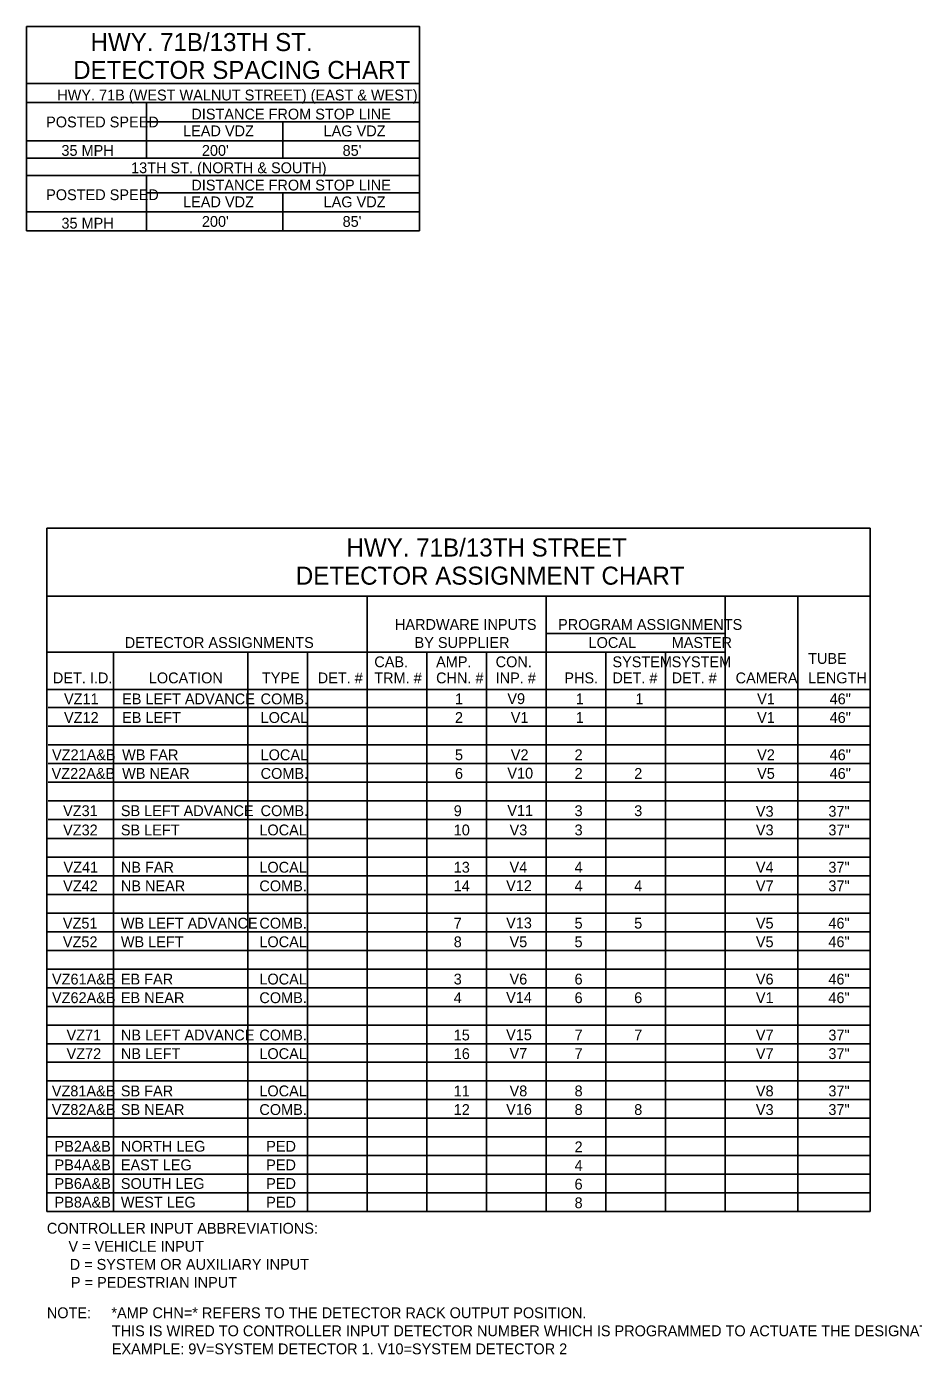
# Model space of a CAD drawing. Extents: x 1 to 35.4, y 0.4 to 10.6.
# Drawn here: x 20.12 to 26.67, y 0.5 to 10.31 of the extents above; entities that cross this region are included whole.
import ezdxf

# ---------------------------------------------------------------- set-up
doc = ezdxf.new("R2010")
doc.units = 0
for name, color, linetype in [('$', 7, 'Continuous'), ('base', 7, 'Continuous'), ('TBLBDR', 7, 'Continuous'), ('TBLLINE', 7, 'Continuous'), ('TBLTEXT', 7, 'Continuous'), ('TEXT', 7, 'Continuous'), ('TITEXT', 7, 'Continuous')]:
    doc.layers.add(name, color=color, linetype=linetype)

msp = doc.modelspace()

# ---------------------------------------------------------------- linework, layer by layer
at = {"layer": 'TBLBDR'}
for p, q in [((20.1154, 9.8904), (20.1154, 8.8027)), ((20.1154, 9.8904), (23.0188, 9.8904)), ((20.1154, 9.8904), (23.0188, 9.8904)), ((23.0188, 8.8027), (23.0188, 9.8904)), ((20.1154, 9.7497), (23.0188, 9.7497)), ((20.1154, 9.3402), (23.0188, 9.3402)), ((20.1154, 9.2122), (23.0188, 9.2122)), ((20.1154, 8.8027), (23.0188, 8.8027)), ((20.2653, 6.6053), (26.3486, 6.6053)), ((20.2653, 1.5569), (20.2653, 6.6053)), ((26.3486, 1.5569), (26.3486, 6.6053)), ((20.2653, 6.1021), (26.3486, 6.1021)), ((22.6328, 1.5569), (22.6328, 6.1021)), ((23.955, 1.5569), (23.955, 6.1021)), ((25.2772, 1.5569), (25.2772, 6.1021)), ((25.8129, 1.5569), (25.8129, 6.1021)), ((23.955, 5.8266), (25.2772, 5.8266)), ((20.2653, 5.6889), (25.2772, 5.6889)), ((20.2653, 5.4134), (26.3486, 5.4134)), ((20.2653, 2.1079), (26.3486, 2.1079)), ((20.2653, 1.5569), (26.3486, 1.5569))]:
    msp.add_line(p, q, dxfattribs=at)
msp.add_lwpolyline([(20.1154, 10.3118), (23.0188, 10.3118), (23.0188, 9.8904), (20.1154, 9.8904)], close=True, dxfattribs=at)
at = {"layer": 'TBLLINE'}
for p, q in [((21.0005, 9.7497), (21.0005, 9.3402)), ((21.0005, 9.6089), (23.0188, 9.6089)), ((22.0097, 9.3402), (22.0097, 9.6089)), ((20.1154, 9.4682), (23.0188, 9.4682)), ((21.0005, 9.2122), (21.0005, 8.8027)), ((21.0005, 9.0842), (22.0097, 9.0842)), ((22.0097, 9.0842), (23.0188, 9.0842)), ((22.0097, 8.8027), (22.0097, 9.0842)), ((20.1154, 8.9435), (23.0188, 8.9435)), ((20.7583, 1.5569), (20.7583, 5.6889)), ((21.7513, 1.5569), (21.7513, 5.6889)), ((22.192, 1.5569), (22.192, 5.6889)), ((23.0735, 1.5569), (23.0735, 5.6889)), ((23.5143, 1.5569), (23.5143, 5.6889)), ((24.3957, 1.5569), (24.3957, 5.6889)), ((24.8365, 1.5569), (24.8365, 5.6889)), ((20.2745, 5.2801), (26.3486, 5.2801)), ((20.2745, 5.1424), (26.3486, 5.1424)), ((20.2745, 5.0046), (26.3486, 5.0046)), ((20.2745, 4.8669), (26.3486, 4.8669)), ((20.2745, 4.7292), (26.3486, 4.7292)), ((20.2745, 4.5914), (26.3486, 4.5914)), ((20.2745, 4.4537), (26.3486, 4.4537)), ((20.2653, 4.3116), (26.3486, 4.3116)), ((20.2653, 4.1738), (26.3486, 4.1738)), ((20.2653, 4.0361), (26.3486, 4.0361)), ((20.2653, 3.8984), (26.3486, 3.8984)), ((20.2653, 3.7606), (26.3486, 3.7606)), ((20.2653, 3.6229), (26.3486, 3.6229)), ((20.2653, 3.4852), (26.3486, 3.4852)), ((20.2653, 3.3474), (26.3486, 3.3474)), ((20.2653, 3.2097), (26.3486, 3.2097)), ((20.2653, 3.072), (26.3486, 3.072)), ((20.2653, 2.9343), (26.3486, 2.9343)), ((20.2653, 2.7965), (26.3486, 2.7965)), ((20.2653, 2.6588), (26.3486, 2.6588)), ((20.2653, 2.5211), (26.3486, 2.5211)), ((20.2653, 2.3833), (26.3486, 2.3833)), ((20.2653, 2.2456), (26.3486, 2.2456)), ((20.2653, 1.9701), (26.3486, 1.9701)), ((20.2653, 1.8324), (26.3486, 1.8324)), ((20.2653, 1.6947), (26.3486, 1.6947))]:
    msp.add_line(p, q, dxfattribs=at)

# ---------------------------------------------------------------- texts
at = {"layer": '$'}
msp.add_text('HWY. 71B/13TH ST.', height=0.133, dxfattribs=at).set_placement((20.5886, 10.1307))
at = {"layer": 'base'}
msp.add_text('DETECTOR SPACING CHART', height=0.133, dxfattribs=at).set_placement((20.4601, 9.9249))
at = {"layer": 'TBLTEXT'}
for s, height, p in [('HWY. 71B (WEST WALNUT STREET) (EAST & WEST)', 0.079995, (20.3421, 9.766)), ('POSTED SPEED', 0.079995, (20.26, 9.5668)), ('DISTANCE FROM STOP LINE', 0.079995, (21.3331, 9.6252)), ('LEAD VDZ', 0.07999, (21.2719, 9.501)), ('LAG VDZ', 0.07999, (22.3101, 9.501)), ('35 MPH', 0.07999, (20.3732, 9.3565)), ("200'", 0.07999, (21.4106, 9.3565)), ("85'", 0.07999, (22.4503, 9.3565)), ('13TH ST. (NORTH & SOUTH)', 0.079995, (20.8876, 9.2285)), ('DISTANCE FROM STOP LINE', 0.079995, (21.3331, 9.1005)), ('POSTED SPEED', 0.079995, (20.26, 9.0293)), ('LEAD VDZ', 0.07999, (21.2719, 8.9763)), ('LAG VDZ', 0.07999, (22.3101, 8.9763)), ('35 MPH', 0.07999, (20.3732, 8.819)), ("200'", 0.07999, (21.4106, 8.8318)), ("85'", 0.07999, (22.4503, 8.8318)), ('HARDWARE INPUTS', 0.079994, (22.8372, 5.8541)), ('PROGRAM ASSIGNMENTS', 0.079994, (24.0422, 5.8541)), ('DETECTOR ASSIGNMENTS', 0.079994, (20.8409, 5.7204)), ('BY SUPPLIER', 0.079994, (22.9822, 5.7204)), ('LOCAL', 0.07999, (24.2679, 5.7204)), ('MASTER', 0.07999, (24.8816, 5.7204)), ('CAB.', 0.07999, (22.6846, 5.578)), ('AMP.', 0.07999, (23.1412, 5.578)), ('CON.', 0.07999, (23.5812, 5.578)), ('SYSTEM', 0.07999, (24.4441, 5.578)), ('SYSTEM', 0.07999, (24.8816, 5.578)), ('TUBE', 0.07999, (25.8899, 5.6028)), ('DET. I.D.', 0.07999, (20.3099, 5.4592)), ('LOCATION', 0.07999, (21.0187, 5.4592)), ('TYPE', 0.07999, (21.854, 5.4592)), ('DET. #', 0.07999, (22.2667, 5.4592)), ('TRM. #', 0.07999, (22.6846, 5.4592)), ('CHN. #', 0.07999, (23.1412, 5.4592)), ('INP. #', 0.07999, (23.5812, 5.4592)), ('PHS.', 0.07999, (24.0887, 5.4592)), ('DET. #', 0.07999, (24.4441, 5.4592)), ('DET. #', 0.07999, (24.8816, 5.4592)), ('CAMERA', 0.07999, (25.3542, 5.4592)), ('LENGTH', 0.07999, (25.8899, 5.4592)), ('CONTROLLER INPUT ABBREVIATIONS:', 0.079994, (20.2653, 1.3927)), ('V = VEHICLE INPUT', 0.079994, (20.4248, 1.2593)), ('D = SYSTEM OR AUXILIARY INPUT', 0.079994, (20.4339, 1.126)), ('P = PEDESTRIAN INPUT', 0.079994, (20.4431, 0.9927)), ('NOTE:', 0.07999, (20.2653, 0.7681)), ('*AMP CHN=* REFERS TO THE DETECTOR RACK OUTPUT POSITION.', 0.079994, (20.7422, 0.7681)), ('THIS IS WIRED TO CONTROLLER INPUT DETECTOR NUMBER WHICH IS PROGRAMMED TO ACTUATE THE DESIGNATED PHASE.', 0.0799944, (20.7453, 0.6348)), ('EXAMPLE: 9V=SYSTEM DETECTOR 1. V10=SYSTEM DETECTOR 2', 0.079994, (20.7453, 0.5015))]:
    msp.add_text(s, height=height, dxfattribs=at).set_placement(p)
at = {"layer": 'TEXT'}
for s, height, p in [('VZ11', 0.07999, (20.3922, 5.3042)), ('EB LEFT ADVANCE', 0.079994, (20.8214, 5.3042)), ('COMB.', 0.07999, (21.8447, 5.3042)), ('1', 0.08, (23.2806, 5.3042)), ('V9', 0.07999, (23.6677, 5.3059)), ('1', 0.08, (24.1733, 5.3042)), ('1', 0.08, (24.6141, 5.3042)), ('V1', 0.07999, (25.5131, 5.3042)), ('46"', 0.07999, (26.0488, 5.3042)), ('VZ12', 0.07999, (20.3922, 5.1664)), ('EB LEFT', 0.07999, (20.8214, 5.1664)), ('LOCAL', 0.07999, (21.8447, 5.1664)), ('2', 0.08, (23.2806, 5.1664)), ('V1', 0.07999, (23.6931, 5.1664)), ('1', 0.08, (24.1733, 5.1664)), ('V1', 0.07999, (25.5131, 5.1664)), ('46"', 0.07999, (26.0488, 5.1664)), ('VZ21A&B', 0.07999, (20.3035, 4.891)), ('WB FAR', 0.07999, (20.8214, 4.891)), ('LOCAL', 0.07999, (21.8447, 4.891)), ('5', 0.08, (23.2806, 4.891)), ('V2', 0.07999, (23.6931, 4.891)), ('2', 0.08, (24.1642, 4.891)), ('V2', 0.07999, (25.5131, 4.891)), ('46"', 0.07999, (26.0488, 4.891)), ('VZ22A&B', 0.07999, (20.3005, 4.7533)), ('WB NEAR', 0.07999, (20.8214, 4.7533)), ('COMB.', 0.07999, (21.8447, 4.7533)), ('6', 0.08, (23.2806, 4.7533)), ('V10', 0.07999, (23.6677, 4.755)), ('2', 0.08, (24.1642, 4.7533)), ('2', 0.08, (24.6049, 4.7533)), ('V5', 0.07999, (25.5131, 4.7533)), ('46"', 0.07999, (26.0488, 4.7533)), ('VZ31', 0.07999, (20.3854, 4.4778)), ('SB LEFT ADVANCE', 0.079994, (20.8122, 4.4778)), ('COMB.', 0.07999, (21.8447, 4.4778)), ('9', 0.08, (23.2715, 4.4778)), ('V11', 0.07999, (23.6677, 4.4795)), ('3', 0.08, (24.1642, 4.4778)), ('3', 0.08, (24.6049, 4.4778)), ('V3', 0.07999, (25.5039, 4.4734)), ('37"', 0.07999, (26.0396, 4.4734)), ('VZ32', 0.07999, (20.3854, 4.3357)), ('SB LEFT', 0.07999, (20.8122, 4.3357)), ('LOCAL', 0.07999, (21.8355, 4.3357)), ('10', 0.07999, (23.2715, 4.3357)), ('V3', 0.07999, (23.6839, 4.3357)), ('3', 0.08, (24.1642, 4.3357)), ('V3', 0.07999, (25.5039, 4.3357)), ('37"', 0.07999, (26.0396, 4.3357)), ('VZ41', 0.07999, (20.3884, 4.0602)), ('NB FAR', 0.07999, (20.8122, 4.0602)), ('LOCAL', 0.07999, (21.8355, 4.0602)), ('13', 0.07999, (23.2715, 4.0602)), ('V4', 0.07999, (23.6839, 4.0602)), ('4', 0.08, (24.1642, 4.0602)), ('V4', 0.07999, (25.5039, 4.0602)), ('37"', 0.07999, (26.0396, 4.0602)), ('VZ42', 0.07999, (20.3857, 3.9225)), ('NB NEAR', 0.07999, (20.8122, 3.9225)), ('COMB.', 0.07999, (21.8355, 3.9225)), ('14', 0.07999, (23.2715, 3.9225)), ('V12', 0.07999, (23.6586, 3.9242)), ('4', 0.08, (24.1642, 3.9225)), ('4', 0.08, (24.6049, 3.9225)), ('V7', 0.07999, (25.5039, 3.9225)), ('37"', 0.07999, (26.0396, 3.9225)), ('V13', 0.07999, (23.6586, 3.6487)), ('VZ51', 0.07999, (20.3838, 3.647)), ('WB LEFT ADVANCE', 0.079994, (20.8122, 3.647)), ('COMB.', 0.07999, (21.8355, 3.647)), ('7', 0.08, (23.2715, 3.647)), ('5', 0.08, (24.1642, 3.647)), ('5', 0.08, (24.6049, 3.647)), ('V5', 0.07999, (25.5039, 3.647)), ('46"', 0.07999, (26.0396, 3.647)), ('VZ52', 0.07999, (20.3838, 3.5093)), ('WB LEFT', 0.07999, (20.8122, 3.5093)), ('LOCAL', 0.07999, (21.8355, 3.5093)), ('8', 0.08, (23.2715, 3.5093)), ('V5', 0.07999, (23.6839, 3.5093)), ('5', 0.08, (24.1642, 3.5093)), ('V5', 0.07999, (25.5039, 3.5093)), ('46"', 0.07999, (26.0396, 3.5093)), ('VZ61A&B', 0.07999, (20.3033, 3.2338)), ('EB FAR', 0.07999, (20.8122, 3.2338)), ('LOCAL', 0.07999, (21.8355, 3.2338)), ('3', 0.08, (23.2715, 3.2338)), ('V6', 0.07999, (23.6839, 3.2338)), ('6', 0.08, (24.1642, 3.2338)), ('V6', 0.07999, (25.5039, 3.2338)), ('46"', 0.07999, (26.0396, 3.2338)), ('VZ62A&B', 0.07999, (20.3033, 3.0961)), ('EB NEAR', 0.07999, (20.8122, 3.0961)), ('COMB.', 0.07999, (21.8355, 3.0961)), ('4', 0.08, (23.2715, 3.0961)), ('V14', 0.07999, (23.6586, 3.0978)), ('6', 0.08, (24.1642, 3.0961)), ('6', 0.08, (24.6049, 3.0961)), ('V1', 0.07999, (25.5039, 3.0961)), ('46"', 0.07999, (26.0396, 3.0961)), ('VZ71', 0.07999, (20.4108, 2.8206)), ('NB LEFT ADVANCE', 0.079994, (20.8122, 2.8206)), ('COMB.', 0.07999, (21.8355, 2.8206)), ('15', 0.07999, (23.2715, 2.8206)), ('V15', 0.07999, (23.6586, 2.8223)), ('7', 0.08, (24.1642, 2.8206)), ('7', 0.08, (24.6049, 2.8206)), ('V7', 0.07999, (25.5039, 2.8206)), ('37"', 0.07999, (26.0396, 2.8206)), ('VZ72', 0.07999, (20.4108, 2.6829)), ('NB LEFT', 0.07999, (20.8122, 2.6829)), ('LOCAL', 0.07999, (21.8355, 2.6829)), ('16', 0.07999, (23.2715, 2.6829)), ('V7', 0.07999, (23.6839, 2.6846)), ('7', 0.08, (24.1642, 2.6829)), ('V7', 0.07999, (25.5039, 2.6829)), ('37"', 0.07999, (26.0396, 2.6829)), ('VZ81A&B', 0.07999, (20.3021, 2.4074)), ('SB FAR', 0.07999, (20.8122, 2.4074)), ('LOCAL', 0.07999, (21.8355, 2.4074)), ('11', 0.07999, (23.2715, 2.4074)), ('V8', 0.07999, (23.6839, 2.4074)), ('8', 0.08, (24.1642, 2.4074)), ('V8', 0.07999, (25.5039, 2.4074)), ('37"', 0.07999, (26.0396, 2.4074)), ('VZ82A&B', 0.07999, (20.3021, 2.2697)), ('SB NEAR', 0.07999, (20.8122, 2.2697)), ('COMB.', 0.07999, (21.8355, 2.2697)), ('12', 0.07999, (23.2715, 2.2697)), ('V16', 0.07999, (23.6586, 2.2714)), ('8', 0.08, (24.1642, 2.2697)), ('8', 0.08, (24.6049, 2.2697)), ('V3', 0.07999, (25.5039, 2.2697)), ('37"', 0.07999, (26.0396, 2.2697)), ('PB2A&B', 0.07999, (20.3222, 1.9986)), ('NORTH LEG', 0.07999, (20.8122, 1.9986)), ('PED', 0.07999, (21.8859, 1.9986)), ('2', 0.08, (24.1642, 1.9942)), ('PB4A&B', 0.07999, (20.3222, 1.8609)), ('EAST LEG', 0.07999, (20.8122, 1.8609)), ('PED', 0.07999, (21.8859, 1.8609)), ('4', 0.08, (24.1642, 1.8565)), ('PB6A&B', 0.07999, (20.3222, 1.7232)), ('SOUTH LEG', 0.07999, (20.8122, 1.7232)), ('PED', 0.07999, (21.8859, 1.7232)), ('6', 0.08, (24.1642, 1.7188)), ('PB8A&B', 0.07999, (20.3222, 1.5854)), ('WEST LEG', 0.07999, (20.8122, 1.5854)), ('PED', 0.07999, (21.8859, 1.5854)), ('8', 0.08, (24.1642, 1.581))]:
    msp.add_text(s, height=height, dxfattribs=at).set_placement(p)
at = {"layer": 'TITEXT'}
for s, p in [('HWY. 71B/13TH STREET', (22.4793, 6.396)), ('DETECTOR ASSIGNMENT CHART', (22.1047, 6.188))]:
    msp.add_text(s, height=0.133324, dxfattribs=at).set_placement(p)

doc.saveas('drawing.dxf')
